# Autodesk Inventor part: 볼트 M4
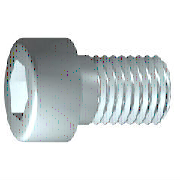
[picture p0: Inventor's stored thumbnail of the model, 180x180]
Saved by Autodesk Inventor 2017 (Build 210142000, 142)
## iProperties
IsCustomPart: 1
Created: 2012-02
Part Number: 볼트 M4
Material: 강철, 연강
Description: 6각머리 태핑 나사
Document SubType Name: Modeling
Standard: KS B 1003
Designer: mduedu
Standards Organization: KS
Language: ko-KR
Size Designation: M 4 x 10
Categories: <MemberInstance><Categories><Category DisplayName="조임쇠" InternalName="e4da775c-781d-43d5-af7c-5136215cf5a6" Mnemonic="FSTN"><Category DisplayName="볼트" InternalN
Density: 7.86 g/cm^3
Mass: 2.0371 g
Surface Area: 3.0572 cm^2
Volume: 0.259174 cm^3
Appearance: 강철
Author: mduedu
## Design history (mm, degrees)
sketch "스케치1"
  geometry: L1 (-1, 0)-(10, 0); L2 (10, 0)-(10, 2); L3 (10, 2)-(1.75, 2); L4 (1.75, 2)-(1.32, 2); L5 (1.32, 2)-(0, 2); L6 (0, 2)-(0, 3.5); L7 (0, 3.5)-(-4, 3.5); L8 (-4, 3.5)-(-4, 1.732); L9 (-4, 1.732)-(-2, 1.732); L10 (-2, 1.732)-(-1, 0); L11 (-6.8, 0)-(12.8, 0) reference; L12 (0, -0.7)-(0, 4.2) reference; L13 (1.75, 2)-(0, 2)
  constraints: 22 end point, 6 parallel, 2 collinear, 2 perpendicular, 1 horizontal, 1 point on line
  dimensions: "d1" = 8.25 distance from line of L3.end L2 (= GEL); "d2" = 0.42952 distance of L4.end L3.end (computed from GAL); "d3" = 4 distance between parallel lines of L8 L6 (= KOH); "d4" = 2 distance of L8.end L9.end (= INTI); "d5" = 60 deg angle of L10 L1; "d6" = 4 diameter of L3 L1 (= GD); "d7" = 4 diameter of L5 L1 (= BDM); "d8" = 3.4641 diameter of L9 L1 (= 1.1547 x SW); "d9" = 7 diameter of L7 L1 (= KOD); "d26" = 10 distance between parallel lines of L12 L2 (= NLG)
revolve "본체" sketch "스케치1" stored, may be unused: angle "d10" = 90 deg
sketch "스케치2"
  geometry: L1 (0, -4.9)-(0, 4.9) reference; L2 (-4.9, 0)-(4.9, 0) reference; L3 (1.732, 0)-(0.866, -1.5); L4 (0.866, -1.5)-(-0.866, -1.5); L5 (-0.866, -1.5)-(-1.732, 0); L6 (-1.732, 0)-(-0.866, 1.5); L7 (-0.866, 1.5)-(0.866, 1.5); L8 (0.866, 1.5)-(1.732, 0); 2 further points
  constraints: 12 end point, 1 coincident, 1 horizontal alignment, 1 point on line, 12 other
extrude "슬롯" join sketch "스케치2" stored distance "d11" = 10; taper "d12" = 0 deg
workplane "Work Plane1"
fillet "Fillet2" dims "d30" = 0.1 (= R)
body "Solid1"
fillet "모깎기1" dims "d17" = 0.4 (= RR)
feature "스레드" dims "d13" = 8.25 (= GEL), "d14" = 0
chamfer "모따기1" distance "d15" = 0.42941 (= -0.5 x SPD + 0.5 x GD); stored, may be unused: second distance "d16" = 0.42941 (= GUL), angle "d27" = 45 deg
other parameters: "GD" = 4 (= NND) [user parameter; used in 2 equation terms], "NLG" = 10 [user parameter; used in 1 equation term], "GEL" = 8.25 [user parameter; used in 2 equation terms], "KOD" = 7 [user parameter; used in 1 equation term], "KOH" = 4 [user parameter; used in 1 equation term], "INTI" = 2 [user parameter; used in 1 equation term], "GAL" = 0.42941 (= 0.61345 x PTC) [user parameter; used in 1 equation term], "GUL" = 0.42941 (= 0.61345 x PTC) [user parameter; used in 1 equation term], "BDM" = 4 (= NND) [user parameter; used in 1 equation term], "SW" = 3 [user parameter; used in 2 equation terms], "RR" = 0.4 [user parameter; used in 1 equation term], "SPD" = 3.14117 (= NND - 1.2269 x PTC) [user parameter; used in 1 equation term], "d19" = 0, "d28" = 0, "d29" = 0, "R" = 0.1 [user parameter; used in 1 equation term], "PHH" = 0.2 [user parameter], "GD1" = 3.14117 (= THREADDIA - 1.2269 x PTC) [user parameter], "THREADDIA" = 4 [user parameter; used in 1 equation term], "FAWI" = 45 deg [user parameter], "TPU" = 14.28571 (computed from PTC) [user parameter], "PTC" = 0.7 [user parameter; used in 5 equation terms], "NND" = 4 [user parameter; used in 3 equation terms], "TOA" = 30 deg [user parameter], "E0" = 3.465 (= 1.155 x SW) [user parameter]
